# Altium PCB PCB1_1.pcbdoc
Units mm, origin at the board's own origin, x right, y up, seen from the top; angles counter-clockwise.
Board outline 210.7 x 47 mm, 2 copper layers (Top Layer, Bottom Layer); 2 components, 6 nets, 20 pads, 48 vias.
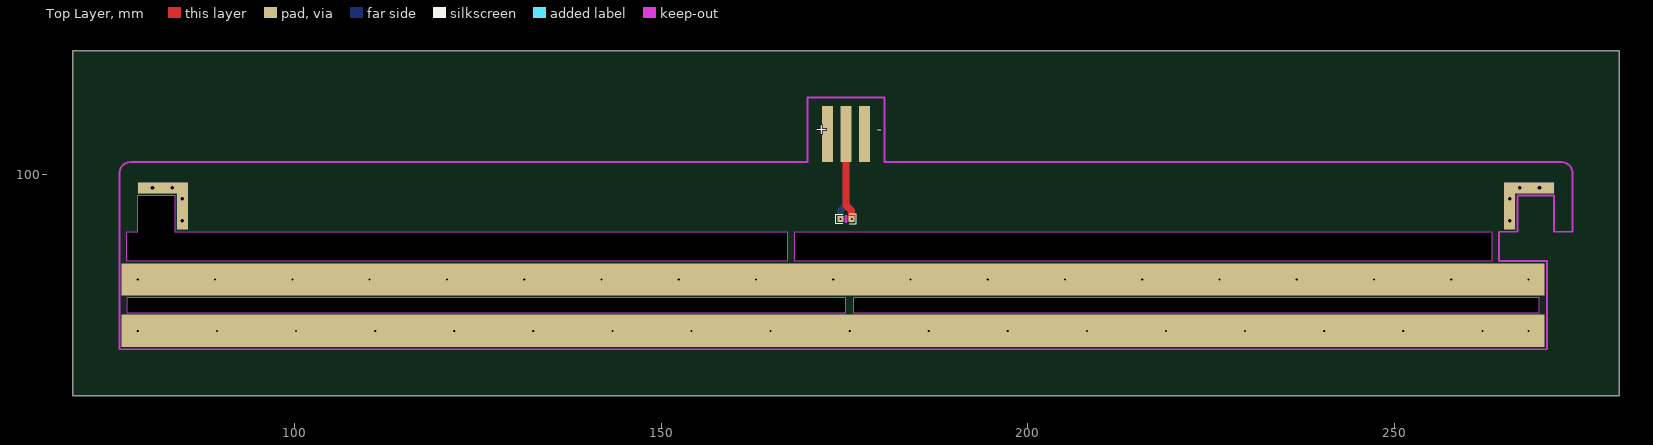
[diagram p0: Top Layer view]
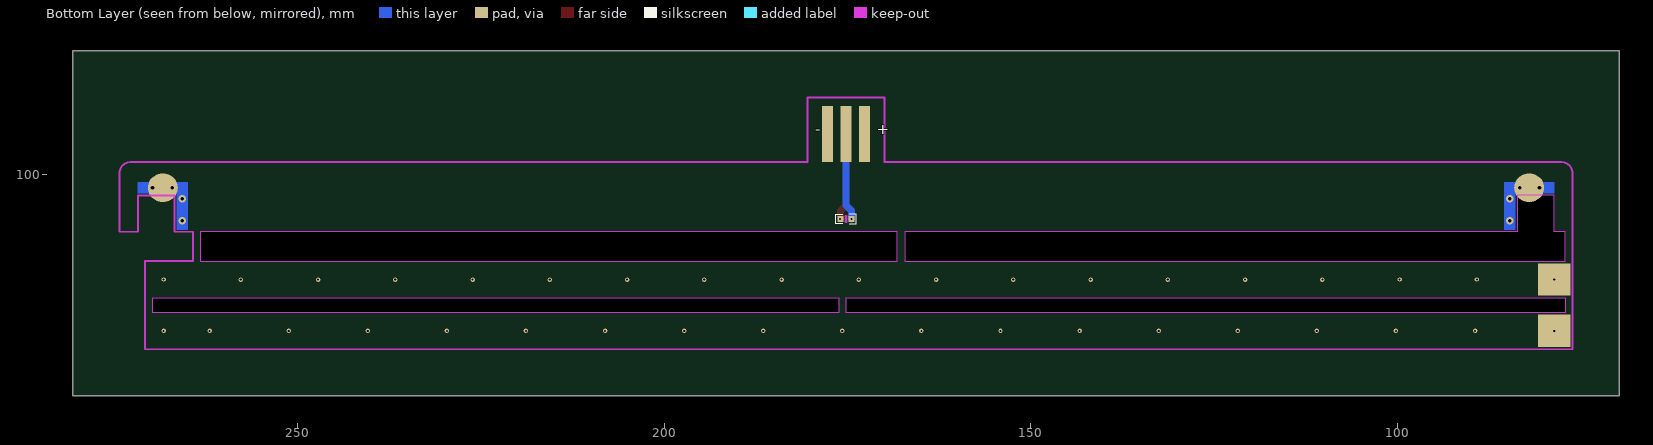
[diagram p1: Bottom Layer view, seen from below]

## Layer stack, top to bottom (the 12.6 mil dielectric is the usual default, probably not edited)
Top Layer: signal copper (thickness not stored)
Dielectric: dielectric 0.32, FR-4, Dk 4.8
Bottom Layer: signal copper (thickness not stored)

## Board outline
280.55,69.85 69.85,69.85 69.85,116.85 280.55,116.85
cut-out: 175.28,93.95 ccw(c175.2,93.948) 175.12,93.95 ccw(c175.2,93.952)
cut-out: 175.28,93.6 ccw(c175.2,93.598) 175.12,93.6 ccw(c175.2,93.602)
cut-out: 175.28,94.3 ccw(c175.2,94.298) 175.12,94.3 ccw(c175.2,94.302)
cut-out: 77.2,81.2 175.2,81.2 175.2,83.2 77.2,83.2
cut-out: 176.2,81.2 269.7,81.2 269.7,83.2 176.2,83.2
cut-out: 77.2,92.2 78.7,92.2 78.7,97.2 83.7,97.2 83.7,92.2 167.2,92.2 167.2,88.2 77.2,88.2
cut-out: 168.2,92.2 263.2,92.2 263.2,88.2 168.2,88.2

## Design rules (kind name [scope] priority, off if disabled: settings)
Clearance copperThickness1oz [All] p1: gap=0.178 ignorepadtopadclearanceinfootprint=FALSE except(0.102: Track-Track; 0.152: Track-SMDPad SMDPad-SMDPad Track-THPad SMDPad-THPad THPad-THPad Track-Via SMDPad-Via THPad-Via Via-Via SMDPad-Fill THPad-Fill Via-Fill Fill-Fill Track-Region SMDPad-Region THPad-Region Via-Region Region-Region Track-Poly SMDPad-Poly THPad-Poly Via-Poly Fill-Poly Region-Poly Poly-Poly Track-Text SMDPad-Text THPad-Text Via-Text Fill-Text Region-Text Poly-Text Text-Text; 0.175: Track-Hole SMDPad-Hole THPad-Hole Via-Hole Fill-Hole Region-Hole Poly-Hole Text-Hole Sheet-Hole; 0.3: Track-Fill Fill-Region Track-Sheet SMDPad-Sheet THPad-Sheet Via-Sheet Fill-Sheet Region-Sheet Poly-Sheet Text-Sheet)
Clearance copperThickness2oz [All] p1: gap=0.178 ignorepadtopadclearanceinfootprint=FALSE except(0.152: Track-SMDPad SMDPad-SMDPad Track-THPad SMDPad-THPad THPad-THPad Track-Via SMDPad-Via THPad-Via Via-Via SMDPad-Fill THPad-Fill Via-Fill Fill-Fill Track-Region SMDPad-Region THPad-Region Via-Region Region-Region Track-Poly SMDPad-Poly THPad-Poly Via-Poly Fill-Poly Region-Poly Poly-Poly Track-Text SMDPad-Text THPad-Text Via-Text Fill-Text Region-Text Poly-Text Text-Text; 0.175: Track-Hole SMDPad-Hole THPad-Hole Via-Hole Fill-Hole Region-Hole Poly-Hole Text-Hole Sheet-Hole; 0.203: Track-Track; 0.3: Track-Fill Fill-Region Track-Sheet SMDPad-Sheet THPad-Sheet Via-Sheet Fill-Sheet Region-Sheet Poly-Sheet Text-Sheet)
DiffPairsRouting differentialPair [All] p1: maxuncoupledlength=10 maxlimit=5.9843 mostfreqgap=5.9843 toplayer_minwidth=5 toplayer_prefwidth=10 toplayer_maxwidth=100 bottomlayer_minwidth=5 bottomlayer_prefwidth=10 bottomlayer_maxwidth=100
PasteMaskExpansion pasteMaskExpansion [All] p1:
PlaneConnect innerPlane [All] p1: planeconnectstyle=Relief reliefexpansion=0.508 reliefentries=4 reliefconductorwidth=0.254 reliefairgap=0.254
PolygonConnect copperRegion [All] p1: connectstyle=Direct reliefentries=4 reliefconductorwidth=10 polygonreliefangle="90 Angle" airgapwidth=10
PolygonConnect copperRegion1 [All] p1: connectstyle=Relief reliefentries=4 reliefconductorwidth=10 polygonreliefangle="90 Angle" airgapwidth=10
PolygonConnect copperRegion2 [All] p1: connectstyle=Relief reliefentries=4 reliefconductorwidth=10 polygonreliefangle="90 Angle" airgapwidth=10
RoutingVias viaSize [All] p1: viastyle="Through Hole" holewidth=12.0078 minholewidth=11.811 maxholewidth=248.0314 width=24.0158 minwidth=19.685 maxwidth=393.7008
SolderMaskExpansion solderMaskExpansion [All] p1: useseparateexpansions=TRUE expansion=2.0079 expansionbottom=2.0079
Width copperThickness1oz [All] p1: maxlimit=100 minlimit=5 preferedwidth=10
Width copperThickness2oz [All] p1: maxlimit=100 minlimit=8 preferedwidth=10

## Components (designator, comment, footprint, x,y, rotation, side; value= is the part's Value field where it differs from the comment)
? "NTC100k" R0603 175.2,93.95 r0 top
? "NTC100k" R0603 175.2,93.95 r180 bottom

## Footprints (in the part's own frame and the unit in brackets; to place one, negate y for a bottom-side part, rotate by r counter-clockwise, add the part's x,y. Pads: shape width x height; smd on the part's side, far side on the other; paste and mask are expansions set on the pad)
R0603 [mm]
  rect 0.806x0.864 smd: 1(-0.753,0) 2(0.753,0)
  silkscreen extent -1.39,-0.66 1.39,0.66

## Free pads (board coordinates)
  rect 4.4x4.4 smd far side: 1(78.7,78.7) 1(78.7,85.7)
  oval 4.08x3.87 smd far side: 1(82.1,98.2) 1(268.3,98.2)
  rect 6.8x1.5 smd: 1(82.1,98.2) 1(268.3,98.2)
  rect 1.5x5 smd: 1(84.75,95) 1(265.65,95)
  rect 1.524x7.65 smd: 1(172.66,105.525) 1(175.2,105.525) 2(177.74,105.525)
  rect 1.524x7.65 smd far side: 1(172.66,105.525) 1(175.2,105.525) 2(177.74,105.525)
  rect 193.9x4.4 smd: 1(173.45,78.7) 1(173.45,85.7)

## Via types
v1: diameter 0.61, hole 0.305, Top Layer to Bottom Layer, 40 vias
v2: diameter 1, hole 0.5, Top Layer to Bottom Layer, 8 vias

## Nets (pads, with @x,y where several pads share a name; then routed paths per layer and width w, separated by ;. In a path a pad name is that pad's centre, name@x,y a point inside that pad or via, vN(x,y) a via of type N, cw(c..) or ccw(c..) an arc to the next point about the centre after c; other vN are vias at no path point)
1: pad.1@78.7,85.7 pad.1@173.45,85.7
  other v1: 78.7,85.7 89.228,85.7 99.756,85.7 110.283,85.698 120.811,85.698 131.339,85.698 141.867,85.698 152.394,85.698 162.922,85.698 173.45,85.698 183.978,85.698 194.506,85.698 205.033,85.698 215.561,85.698 226.089,85.698 236.617,85.698 247.144,85.698 257.672,85.698 268.2,85.7
2: 
3: pad.1@265.65,95 pad.1@268.3,98.2 pad.2
  other v2: 265.65,93.7 265.65,96.7 267,98.2 269.7,98.2
11: pad.1@78.7,78.7 pad.1@173.45,78.7
  other v1: 78.7,78.7 89.478,78.7 100.256,78.7 111.033,78.698 121.811,78.698 132.589,78.698 143.367,78.698 154.144,78.698 164.922,78.698 175.7,78.698 186.478,78.698 197.256,78.698 208.033,78.698 218.811,78.698 229.589,78.698 240.367,78.698 251.144,78.698 261.922,78.698 268.2,78.7
R1: ?.1@174.447,93.95 ?.2@174.447,93.95 pad.1@175.2,105.525 | length 11.9
  Bottom Layer w1: v1(174.447,93.95) 174.447,95.061 175.2,95.814 pad.1@175.2,105.525
R2: ?.1@175.953,93.95 ?.2@175.953,93.95 pad.1@175.2,105.525 | length 11.9
  Top Layer w1: pad.1@175.2,105.525 175.2,95.814 175.953,95.061 ?.2@175.953,93.95
  other v1: 176,93.95
copper on no net:
  other v2: 84.75,93.7 84.75,96.7 80.7,98.2 83.4,98.2

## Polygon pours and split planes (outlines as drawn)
1 on Bottom Layer (solid, remove dead copper, pour order 8): 76.45,83.45 270.45,83.45 270.45,87.95 76.45,87.95
11 on Bottom Layer (solid, remove dead copper, pour order 10): 76.45,76.45 270.45,76.45 270.45,80.95 76.45,80.95
1 on Top Layer (solid, remove dead copper): 76.45,83.45 270.45,83.45 270.45,87.95 76.45,87.95
11 on Top Layer (solid, remove dead copper, pour order 2): 76.45,76.45 270.45,76.45 270.45,80.95 76.45,80.95
3 on Bottom Layer (solid, remove dead copper, pour order 14): 176.4,92.5 274.2,92.5 274.2,110.5 176.4,110.5
3 on Bottom Layer (solid, remove dead copper, pour order 12): 176.4,92.5 274.2,92.5 274.2,110.5 176.4,110.5
no net on Bottom Layer (solid, remove dead copper, pour order 16): 76.2,92.5 174,92.5 174,110.5 76.2,110.5
no net on Bottom Layer (solid, remove dead copper, pour order 18): 76.2,92.5 174,92.5 174,110.5 76.2,110.5
3 on Top Layer (solid, remove dead copper, pour order 6): 176.4,92.5 274.2,92.5 274.2,110.5 176.4,110.5
no net on Top Layer (solid, remove dead copper, pour order 4): 76.2,92.5 174,92.5 174,110.5 76.2,110.5

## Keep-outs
Board Outline Layer:
  lines w0.254: 76.2,76.2 270.705,76.2 270.705,88.2 264.2,88.2 264.2,92.2 266.7,92.2 266.7,97.149 271.7,97.149 271.7,92.2 274.2,92.2 274.2,100.2 ccw(c272.7,100.2) 272.7,101.7 180.45,101.7 180.45,110.5 169.95,110.5 169.95,101.7 77.7,101.7 ccw(c77.7,100.2) 76.2,100.2 76.2,76.2
Multi-Layer:
  circle w0.254: c175.2,93.95 r0.08
  circle w0.254: c175.2,93.6 r0.08
  circle w0.254: c175.2,94.3 r0.08
  region: 77.2,81.2 175.2,81.2 175.2,83.2 77.2,83.2
  region: 176.2,81.2 269.7,81.2 269.7,83.2 176.2,83.2
  region: 77.2,92.2 78.7,92.2 78.7,97.2 83.7,97.2 83.7,92.2 167.2,92.2 167.2,88.2 77.2,88.2
  region: 168.2,92.2 263.2,92.2 263.2,88.2 168.2,88.2

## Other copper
Bottom Layer:
  region: 84,92.5 84,97.45 78.7,97.45 78.7,98.95 85.5,98.95 85.5,92.5
  region net 3: 271.7,97.45 266.4,97.45 266.4,92.5 264.9,92.5 264.9,98.95 271.7,98.95

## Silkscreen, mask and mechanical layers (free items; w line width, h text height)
Top Silkscreen Layer:
  text "+" at 170.995,105.51 h1.5
  text "-" at 179.377,105.51 h1.5
Bottom Silkscreen Layer:
  text "+" at 170.995,105.51 h1.5
  text "-" at 179.377,105.51 h1.5
Mechanical Layer:
  circle w0.025: c175.2,93.95 r0.08
  circle w0.025: c175.2,93.6 r0.08
  circle w0.025: c175.2,94.3 r0.08
  lines w0.025: 77.2,81.2 175.2,81.2 175.2,83.2 77.2,83.2 77.2,81.2 ; 77.2,88.2 167.2,88.2 167.2,92.2 83.7,92.2 83.7,97.2 78.7,97.2 78.7,92.2 77.2,92.2 77.2,88.2 ; 168.2,88.2 263.2,88.2 263.2,92.2 168.2,92.2 168.2,88.2 ; 176.2,81.2 269.7,81.2 269.7,83.2 176.2,83.2 176.2,81.2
